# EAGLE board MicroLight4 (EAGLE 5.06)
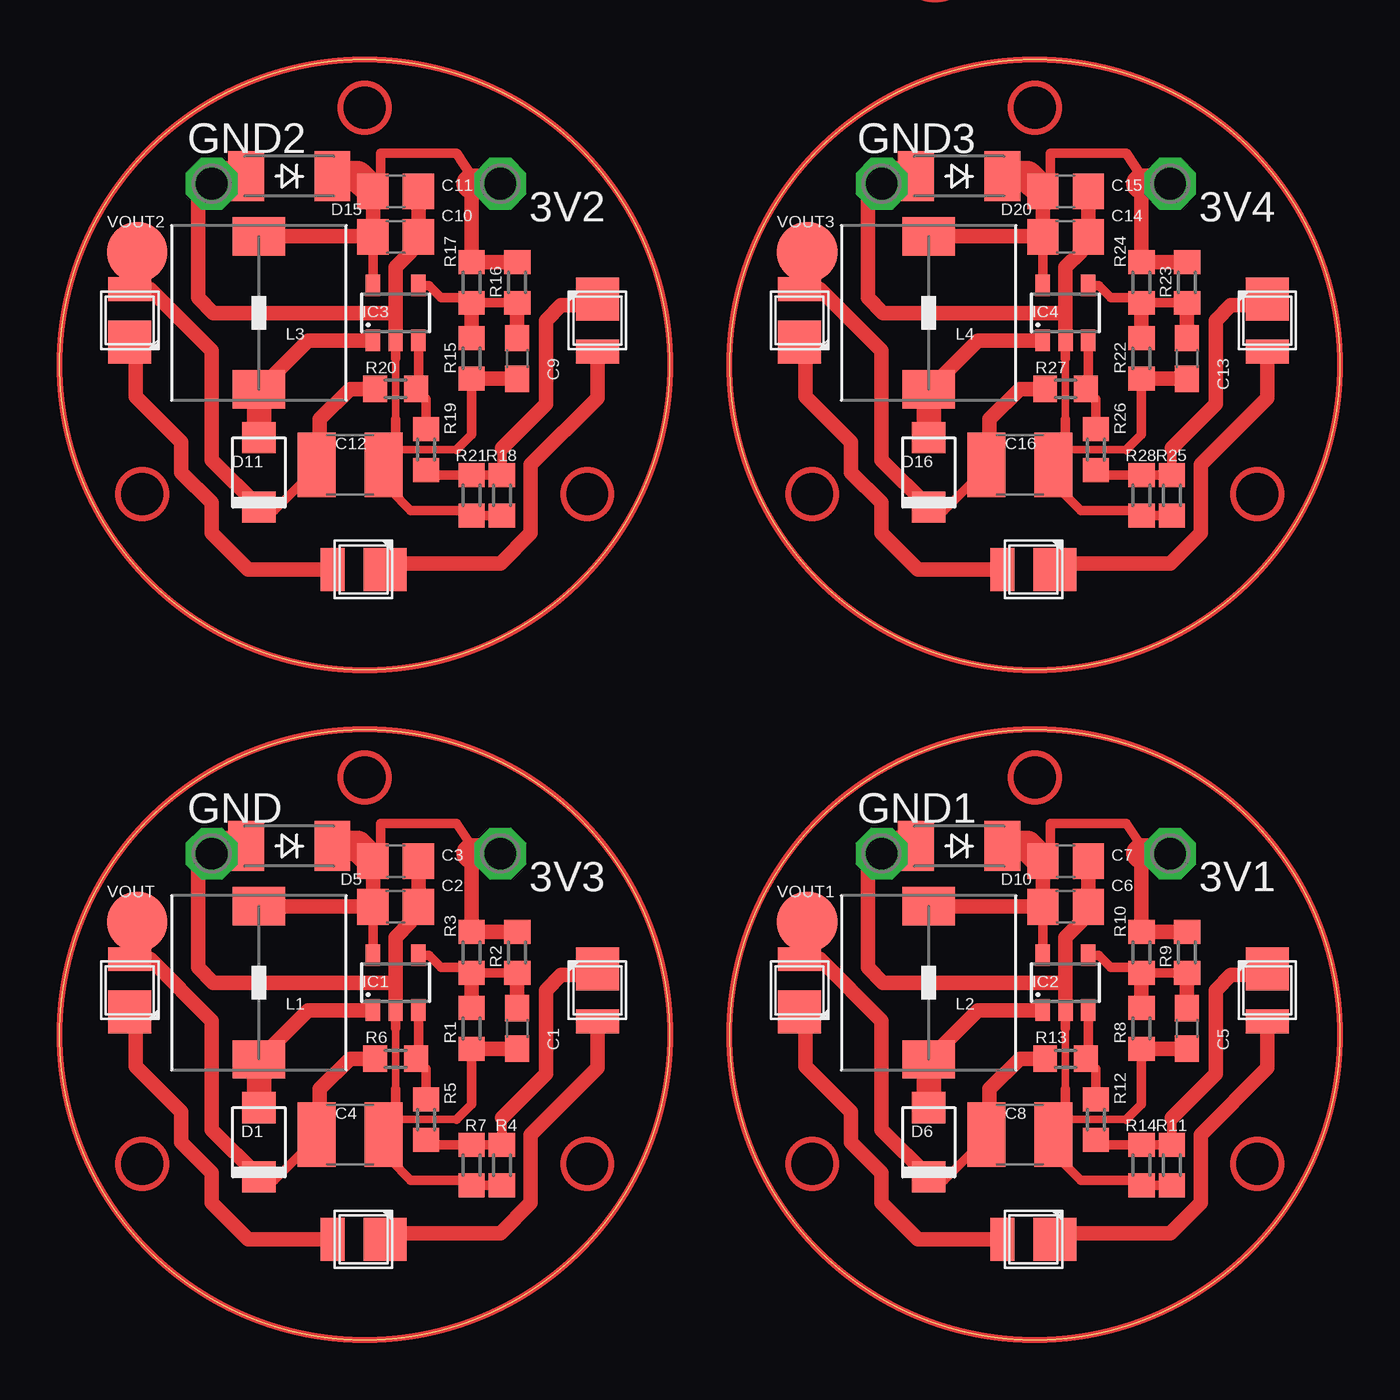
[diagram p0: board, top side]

Size 53.5 x 53.5 mm. Coordinates in mm from the lower left corner, seen from the top.
Outline: circle at 12.75,12.75 radius 12.75
Outline: circle at 40.75,12.75 radius 12.75
Outline: circle at 12.75,40.75 radius 12.75
Outline: circle at 40.75,40.75 radius 12.75
Copper layers (1*16): Top 0.035mm / dielectric 1.5mm / Bottom 0.035mm
Design rules "default": minimum track width 10mil, minimum drill 24mil, track to track 8mil, track to pad 8mil, pad to pad 8mil, via to via 8mil, smd to smd 8mil, copper to edge 40mil, drill to drill 8mil, minimum pad ring 10mil, minimum via ring 8mil, stop-mask expansion 4mil, vias tented up to drill 0mil, thermal gap 10mil

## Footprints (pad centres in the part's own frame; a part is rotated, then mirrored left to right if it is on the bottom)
P1-13 = drill 1.321 pad 2.159 octagon: 1 0,0
C0603 = smd 1.1 x 1: 1 -0.85,0; 2 0.85,0
C0805 = smd 1.3 x 1.5: 1 -0.95,0; 2 0.95,0
C1210 = smd 1.6 x 2.7: 1 -1.4,0; 2 1.4,0
DO219 = smd 1.3 x 1.4: A 1.45,0; K -1.45,0
LED_KAI = smd 1.8 x 1: A 1.2,-0.1 | smd 1.8 x 1.8: K 1.2,2.1
SOD-123_MINI-SMA = smd 1.5 x 2.1: A 1.8,0; C -1.8,0
SOT23-5 = smd 0.6 x 0.9: 1 -0.95,-1.15; 2 0,-1.15; 3 0.95,-1.15; 4 0.95,1.15; 5 -0.95,1.15
WE-PD_S/M = smd 1.6 x 2.2: 1 -3.2,0; 2 3.2,0
R0603 = smd 1 x 1.1: 1 -0.85,0; 2 0.85,0
B2,54 = smd 2.54 x 2.54: PP 0,0

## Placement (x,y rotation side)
3V1  TPPAD1-13  [P1-13]  46.41,20.32 0 top
3V2  TPPAD1-13  [P1-13]  18.41,48.32 0 top
3V3  TPPAD1-13  [P1-13]  18.41,20.32 0 top
3V4  TPPAD1-13  [P1-13]  46.41,48.32 0 top
C1  100nF  [C0603]  19.12,13.02 270 top
C2  10uF  [C0805]  14.04,18.09 0 top
C3  10uF  [C0805]  14.04,20 0 top
C4  10uF  [C1210]  12.13,8.57 0 top
C5  100nF  [C0603]  47.12,13.02 270 top
C6  10uF  [C0805]  42.04,18.09 0 top
C7  10uF  [C0805]  42.04,20 0 top
C8  10uF  [C1210]  40.13,8.57 0 top
C9  100nF  [C0603]  19.12,41.02 270 top
C10  10uF  [C0805]  14.04,46.09 0 top
C11  10uF  [C0805]  14.04,48 0 top
C12  10uF  [C1210]  12.13,36.57 0 top
C13  100nF  [C0603]  47.12,41.02 270 top
C14  10uF  [C0805]  42.04,46.09 0 top
C15  10uF  [C0805]  42.04,48 0 top
C16  10uF  [C1210]  40.13,36.57 0 top
D1  SL04  [DO219]  8.32,8.25 90 top
D2  weiss  [LED_KAI]  21.27,13.4 0 top
D3  weiss  [LED_KAI]  11.5,5.39 270 top
D4  weiss  [LED_KAI]  4.12,15.81 180 top
D5  CGRM4001  [SOD-123_MINI-SMA]  9.59,20.64 180 top
D6  SL04  [DO219]  36.32,8.25 90 top
D7  weiss  [LED_KAI]  49.27,13.4 0 top
D8  weiss  [LED_KAI]  39.5,5.39 270 top
D9  weiss  [LED_KAI]  32.12,15.81 180 top
D10  CGRM4001  [SOD-123_MINI-SMA]  37.59,20.64 180 top
D11  SL04  [DO219]  8.32,36.25 90 top
D12  weiss  [LED_KAI]  21.27,41.4 0 top
D13  weiss  [LED_KAI]  11.5,33.4 270 top
D14  weiss  [LED_KAI]  4.12,43.81 180 top
D15  CGRM4001  [SOD-123_MINI-SMA]  9.59,48.63 180 top
D16  SL04  [DO219]  36.32,36.25 90 top
D17  weiss  [LED_KAI]  49.27,41.4 0 top
D18  weiss  [LED_KAI]  39.5,33.4 270 top
D19  weiss  [LED_KAI]  32.12,43.81 180 top
D20  CGRM4001  [SOD-123_MINI-SMA]  37.59,48.63 180 top
GND  TPPAD1-13  [P1-13]  6.35,20.32 0 top
GND1  TPPAD1-13  [P1-13]  34.35,20.32 0 top
GND2  TPPAD1-13  [P1-13]  6.35,48.32 0 top
GND3  TPPAD1-13  [P1-13]  34.35,48.32 0 top
IC1  LT1615  [SOT23-5]  14.04,14.92 0 top
IC2  LT1615  [SOT23-5]  42.04,14.92 0 top
IC3  LT1615  [SOT23-5]  14.04,42.92 0 top
IC4  LT1615  [SOT23-5]  42.04,42.92 0 top
L1  10uH  [WE-PD_S/M]  8.32,14.92 90 top
L2  10uH  [WE-PD_S/M]  36.32,14.92 90 top
L3  10uH  [WE-PD_S/M]  8.32,42.92 90 top
L4  10uH  [WE-PD_S/M]  36.32,42.92 90 top
R1  18k  [R0603]  17.21,13.02 90 top
R2  56k  [R0603]  19.12,16.19 90 top
R3  180k  [R0603]  17.21,16.19 90 top
R4  33R  [R0603]  18.48,7.3 90 top
R5  10k  [R0603]  15.31,9.21 90 top
R6  100k  [R0603]  14.04,11.74 0 top
R7  33R  [R0603]  17.21,7.3 90 top
R8  18k  [R0603]  45.21,13.02 90 top
R9  56k  [R0603]  47.12,16.19 90 top
R10  180k  [R0603]  45.21,16.19 90 top
R11  33R  [R0603]  46.48,7.3 90 top
R12  10k  [R0603]  43.31,9.21 90 top
R13  100k  [R0603]  42.04,11.74 0 top
R14  33R  [R0603]  45.21,7.3 90 top
R15  18k  [R0603]  17.21,41.02 90 top
R16  56k  [R0603]  19.12,44.19 90 top
R17  180k  [R0603]  17.21,44.19 90 top
R18  33R  [R0603]  18.48,35.3 90 top
R19  10k  [R0603]  15.31,37.2 90 top
R20  100k  [R0603]  14.04,39.74 0 top
R21  33R  [R0603]  17.21,35.3 90 top
R22  18k  [R0603]  45.21,41.02 90 top
R23  56k  [R0603]  47.12,44.19 90 top
R24  180k  [R0603]  45.21,44.19 90 top
R25  33R  [R0603]  46.48,35.3 90 top
R26  10k  [R0603]  43.31,37.2 90 top
R27  100k  [R0603]  42.04,39.74 0 top
R28  33R  [R0603]  45.21,35.3 90 top
VOUT  [B2,54]  3.24,17.46 0 top
VOUT1  [B2,54]  31.24,17.46 0 top
VOUT2  [B2,54]  3.24,45.46 0 top
VOUT3  [B2,54]  31.24,45.46 0 top

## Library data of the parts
3V1-3V4 GND GND1-GND3 VOUT VOUT1-VOUT3 = testpad
C1-C16 R1-R28 = rcl
D1-D4 D6-D9 D11-D14 D16-D19 IC1-IC4 = olaf_V5
D5 D10 D15 D20 = diode
L1-L4 = wuerth-elektronik

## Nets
+3V1: 3V1.1 C6.1 C7.1 D10.C IC2.5 L2.2 R9.2 R10.2
+3V2: 3V2.1 C10.1 C11.1 D15.C IC3.5 L3.2 R16.2 R17.2
+3V3: 3V3.1 C2.1 C3.1 D5.C IC1.5 L1.2 R2.2 R3.2
+3V4: 3V4.1 C14.1 C15.1 D20.C IC4.5 L4.2 R23.2 R24.2
GND: C1.2 C2.2 C3.2 C4.2 D5.A GND.1 IC1.2 R1.1 R4.1 R7.1
GND1: C5.2 C6.2 C7.2 C8.2 D10.A GND1.1 IC2.2 R8.1 R11.1 R14.1
GND2: C9.2 C10.2 C11.2 C12.2 D15.A GND2.1 IC3.2 R15.1 R18.1 R21.1
GND3: C13.2 C14.2 C15.2 C16.2 D20.A GND3.1 IC4.2 R22.1 R25.1 R28.1
N$1: IC2.3 R12.2 R13.2
N$2: IC1.3 R5.2 R6.2
N$3: D2.K R4.2 R5.1 R7.2
N$4: C4.1 D1.K D4.A R6.1 VOUT.PP
N$5: D1.A IC1.1 L1.1
N$6: C1.1 IC1.4 R1.2 R2.1 R3.1
N$7: D3.A D4.K
N$8: D7.K R11.2 R12.1 R14.2
N$9: D2.A D3.K
N$10: C8.1 D6.K D9.A R13.1 VOUT1.PP
N$11: D6.A IC2.1 L2.1
N$12: C5.1 IC2.4 R8.2 R9.1 R10.1
N$13: D8.A D9.K
N$14: D7.A D8.K
N$15: IC3.3 R19.2 R20.2
N$16: D12.K R18.2 R19.1 R21.2
N$17: C12.1 D11.K D14.A R20.1 VOUT2.PP
N$18: D11.A IC3.1 L3.1
N$19: C9.1 IC3.4 R15.2 R16.1 R17.1
N$20: D13.A D14.K
N$21: D12.A D13.K
N$22: IC4.3 R26.2 R27.2
N$23: D17.K R25.2 R26.1 R28.2
N$24: C16.1 D16.K D19.A R27.1 VOUT3.PP
N$25: D16.A IC4.1 L4.1
N$26: C13.1 IC4.4 R22.2 R23.1 R24.1
N$27: D18.A D19.K
N$28: D17.A D18.K

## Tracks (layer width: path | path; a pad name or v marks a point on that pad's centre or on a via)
+3V1
  Top 0.406: IC2.5 C6.1 41.09,18.12 | 45.21,20.32 45.21,20.64 44.58,21.59 41.4,21.59 41.4,20.32 C7.1
  Top 0.61: C6.1 C7.1 | L2.2 41.09,18.12 | 45.21,20.32 R10.2 R9.2
  Top 1.27: D10.C 40.45,20.64 C7.1 | 45.21,20.32 3V1.1
+3V2
  Top 0.406: IC3.5 C10.1 13.09,46.12 | 17.21,48.32 17.21,48.63 16.58,49.59 13.4,49.59 13.4,48.31 C11.1
  Top 0.61: C10.1 C11.1 | L3.2 13.09,46.12 | 17.21,48.32 R17.2 R16.2
  Top 1.27: D15.C 12.45,48.63 C11.1 | 17.21,48.32 3V2.1
+3V3
  Top 0.406: IC1.5 C2.1 13.09,18.12 | 17.21,20.32 17.21,20.64 16.58,21.59 13.4,21.59 13.4,20.32 C3.1
  Top 0.61: C2.1 C3.1 | L1.2 13.09,18.12 | 17.21,20.32 R3.2 R2.2
  Top 1.27: D5.C 12.45,20.64 C3.1 | 17.21,20.32 3V3.1
+3V4
  Top 0.406: IC4.5 C14.1 41.09,46.12 | 45.21,48.32 45.21,48.63 44.58,49.59 41.4,49.59 41.4,48.31 C15.1
  Top 0.61: C14.1 C15.1 | L4.2 41.09,46.12 | 45.21,48.32 R24.2 R23.2
  Top 1.27: D20.C 40.45,48.63 C15.1 | 45.21,48.32 3V4.1
GND
  Top 0.305: 14.04,13.02 14.04,10.47 | 14.04,9.21 16.58,9.21
  Top 0.406: 14.67,17.46 14.67,17.78 C2.2 | IC1.2 14.04,13.02 | 14.04,10.47 14.04,9.21 14.04,9.07 C4.2 13.82,8.28 13.82,7.51 14.67,6.67 17,6.67 R7.1 R4.1 | R1.1 17.21,9.84 16.58,9.21 | 5.78,20.25 GND.1 6.03,20.64
  Top 0.61: C2.2 C3.2 | 14.04,14.92 IC1.2 | 14.04,14.92 14.04,16.82 14.67,17.46 | R1.1 C1.2 | 14.04,14.92 6.42,14.92 5.78,15.55 5.78,20.25
  Top 1.27: 6.03,20.64 D5.A
GND1
  Top 0.305: 42.04,13.02 42.04,10.47 | 42.04,9.21 44.58,9.21
  Top 0.406: 42.67,17.46 42.67,17.78 C6.2 | IC2.2 42.04,13.02 | 42.04,10.47 42.04,9.21 42.04,9.07 C8.2 41.82,8.28 41.82,7.51 42.67,6.67 45,6.67 R14.1 R11.1 | R8.1 45.21,9.84 44.58,9.21 | 33.78,20.25 GND1.1 34.03,20.64
  Top 0.61: C6.2 C7.2 | 42.04,14.92 IC2.2 | 42.04,14.92 42.04,16.82 42.67,17.46 | R8.1 C5.2 | 42.04,14.92 34.42,14.92 33.78,15.55 33.78,20.25
  Top 1.27: 34.03,20.64 D10.A
GND2
  Top 0.305: 14.04,41.02 14.04,38.48 | 14.04,37.2 16.58,37.2
  Top 0.406: 14.67,45.46 14.67,45.78 C10.2 | IC3.2 14.04,41.02 | 14.04,38.48 14.04,37.2 14.04,37.08 C12.2 13.82,36.28 13.82,35.52 14.67,34.66 17,34.66 R21.1 R18.1 | R15.1 17.21,37.84 16.58,37.2 | 5.78,48.25 GND2.1 6.03,48.63
  Top 0.61: C10.2 C11.2 | 14.04,42.92 IC3.2 | 14.04,42.92 14.04,44.83 14.67,45.46 | R15.1 C9.2 | 14.04,42.92 6.42,42.92 5.78,43.55 5.78,48.25
  Top 1.27: 6.03,48.63 D15.A
GND3
  Top 0.305: 42.04,41.02 42.04,38.48 | 42.04,37.2 44.58,37.2
  Top 0.406: 42.67,45.46 42.67,45.78 C14.2 | IC4.2 42.04,41.02 | 42.04,38.48 42.04,37.2 42.04,37.08 C16.2 41.82,36.28 41.82,35.52 42.67,34.66 45,34.66 R28.1 R25.1 | R22.1 45.21,37.84 44.58,37.2 | 33.78,48.25 GND3.1 34.03,48.63
  Top 0.61: C14.2 C15.2 | 42.04,42.92 IC4.2 | 42.04,42.92 42.04,44.83 42.67,45.46 | R22.1 C13.2 | 42.04,42.92 34.42,42.92 33.78,43.55 33.78,48.25
  Top 1.27: 34.03,48.63 D20.A
N$1
  Top 0.406: IC2.3 42.99,11.85 R13.2 43.31,11.32 R12.2
N$2
  Top 0.406: IC1.3 14.99,11.85 R6.2 15.31,11.32 R5.2
N$3
  Top 0.406: R5.1 15.52,8.14 R7.2 R4.2 18.48,9.28 | 22.21,15.24 D2.K
  Top 0.61: 18.48,9.28 20.32,11.11 20.32,14.61 20.95,15.24 22.21,15.24
N$4
  Top 0.406: 10.86,8.7 C4.1 10.73,8.44 8.96,6.67 8.5,6.67 D1.K | 3.78,15.91 D4.A 3.24,16.23
  Top 0.61: R6.1 12.13,11.74 10.86,10.47 10.86,8.7 | 3.78,15.91 6.35,13.34 6.35,8.78 D1.K | VOUT.PP 3.24,16.23
N$5
  Top 0.61: IC1.1 10.37,13.77 L1.1
  Top 1.016: D1.A L1.1
N$6
  Top 0.406: IC1.4 15.43,16.07 15.94,15.55 17,15.55 R3.1 R2.1
  Top 0.61: R2.1 C1.1 | R3.1 R1.2
N$7
  Top 0.406: 3.17,13.46 D4.K
  Top 0.61: D3.A 7.87,4.2 6.35,5.71 6.35,6.99 5.08,8.26 5.08,9.53 3.17,11.43 3.17,13.46
N$8
  Top 0.406: R12.1 43.52,8.14 R14.2 R11.2 46.48,9.28 | 50.21,15.24 D7.K
  Top 0.61: 46.48,9.28 48.32,11.11 48.32,14.61 48.95,15.24 50.21,15.24
N$9
  Top 0.406: 13.85,4.45 D3.K
  Top 0.61: D2.A 22.48,11.36 19.68,8.57 19.68,5.71 18.41,4.45 13.85,4.45
N$10
  Top 0.406: 38.86,8.7 C8.1 38.73,8.44 36.96,6.67 36.5,6.67 D6.K | 31.78,15.91 D9.A 31.24,16.23
  Top 0.61: R13.1 40.13,11.74 38.86,10.47 38.86,8.7 | 31.78,15.91 34.35,13.34 34.35,8.78 D6.K | VOUT1.PP 31.24,16.23
N$11
  Top 0.61: IC2.1 38.37,13.77 L2.1
  Top 1.016: D6.A L2.1
N$12
  Top 0.406: IC2.4 43.43,16.07 43.94,15.55 45,15.55 R10.1 R9.1
  Top 0.61: R9.1 C5.1 | R10.1 R8.2
N$13
  Top 0.406: 31.18,13.46 D9.K
  Top 0.61: D8.A 35.87,4.2 34.35,5.71 34.35,6.99 33.08,8.26 33.08,9.53 31.18,11.43 31.18,13.46
N$14
  Top 0.406: 41.85,4.45 D8.K
  Top 0.61: D7.A 50.48,11.36 47.69,8.57 47.69,5.71 46.41,4.45 41.85,4.45
N$15
  Top 0.406: IC3.3 14.99,39.84 R20.2 15.31,39.33 R19.2
N$16
  Top 0.406: R19.1 15.52,36.14 R21.2 R18.2 18.48,37.27 | 22.21,43.24 D12.K
  Top 0.61: 18.48,37.27 20.32,39.11 20.32,42.6 20.95,43.24 22.21,43.24
N$17
  Top 0.406: 10.86,36.7 C12.1 10.73,36.44 8.96,34.66 8.5,34.66 D11.K | 3.78,43.91 D14.A 3.24,44.23
  Top 0.61: R20.1 12.13,39.74 10.86,38.48 10.86,36.7 | 3.78,43.91 6.35,41.34 6.35,36.77 D11.K | VOUT2.PP 3.24,44.23
N$18
  Top 0.61: IC3.1 10.37,41.77 L3.1
  Top 1.016: D11.A L3.1
N$19
  Top 0.406: IC3.4 15.43,44.07 15.94,43.55 17,43.55 R17.1 R16.1
  Top 0.61: R16.1 C9.1 | R17.1 R15.2
N$20
  Top 0.406: 3.17,41.46 D14.K
  Top 0.61: D13.A 7.87,32.2 6.35,33.72 6.35,34.98 5.08,36.26 5.08,37.52 3.17,39.43 3.17,41.46
N$21
  Top 0.406: 13.85,32.45 D13.K
  Top 0.61: D12.A 22.48,39.36 19.68,36.57 19.68,33.72 18.41,32.45 13.85,32.45
N$22
  Top 0.406: IC4.3 42.99,39.84 R27.2 43.31,39.33 R26.2
N$23
  Top 0.406: R26.1 43.52,36.14 R28.2 R25.2 46.48,37.27 | 50.21,43.24 D17.K
  Top 0.61: 46.48,37.27 48.32,39.11 48.32,42.6 48.95,43.24 50.21,43.24
N$24
  Top 0.406: 38.86,36.7 C16.1 38.73,36.44 36.96,34.66 36.5,34.66 D16.K | 31.78,43.91 D19.A 31.24,44.23
  Top 0.61: R27.1 40.13,39.74 38.86,38.48 38.86,36.7 | 31.78,43.91 34.35,41.34 34.35,36.77 D16.K | VOUT3.PP 31.24,44.23
N$25
  Top 0.61: IC4.1 38.37,41.77 L4.1
  Top 1.016: D16.A L4.1
N$26
  Top 0.406: IC4.4 43.43,44.07 43.94,43.55 45,43.55 R24.1 R23.1
  Top 0.61: R23.1 C13.1 | R24.1 R22.2
N$27
  Top 0.406: 31.18,41.46 D19.K
  Top 0.61: D18.A 35.87,32.2 34.35,33.72 34.35,34.98 33.08,36.26 33.08,37.52 31.18,39.43 31.18,41.46
N$28
  Top 0.406: 41.85,32.45 D18.K
  Top 0.61: D17.A 50.48,39.36 47.69,36.57 47.69,33.72 46.41,32.45 41.85,32.45
(copper drawn outside any net)
  shapes: Top circle x16

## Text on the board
Top: Bestueckung!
